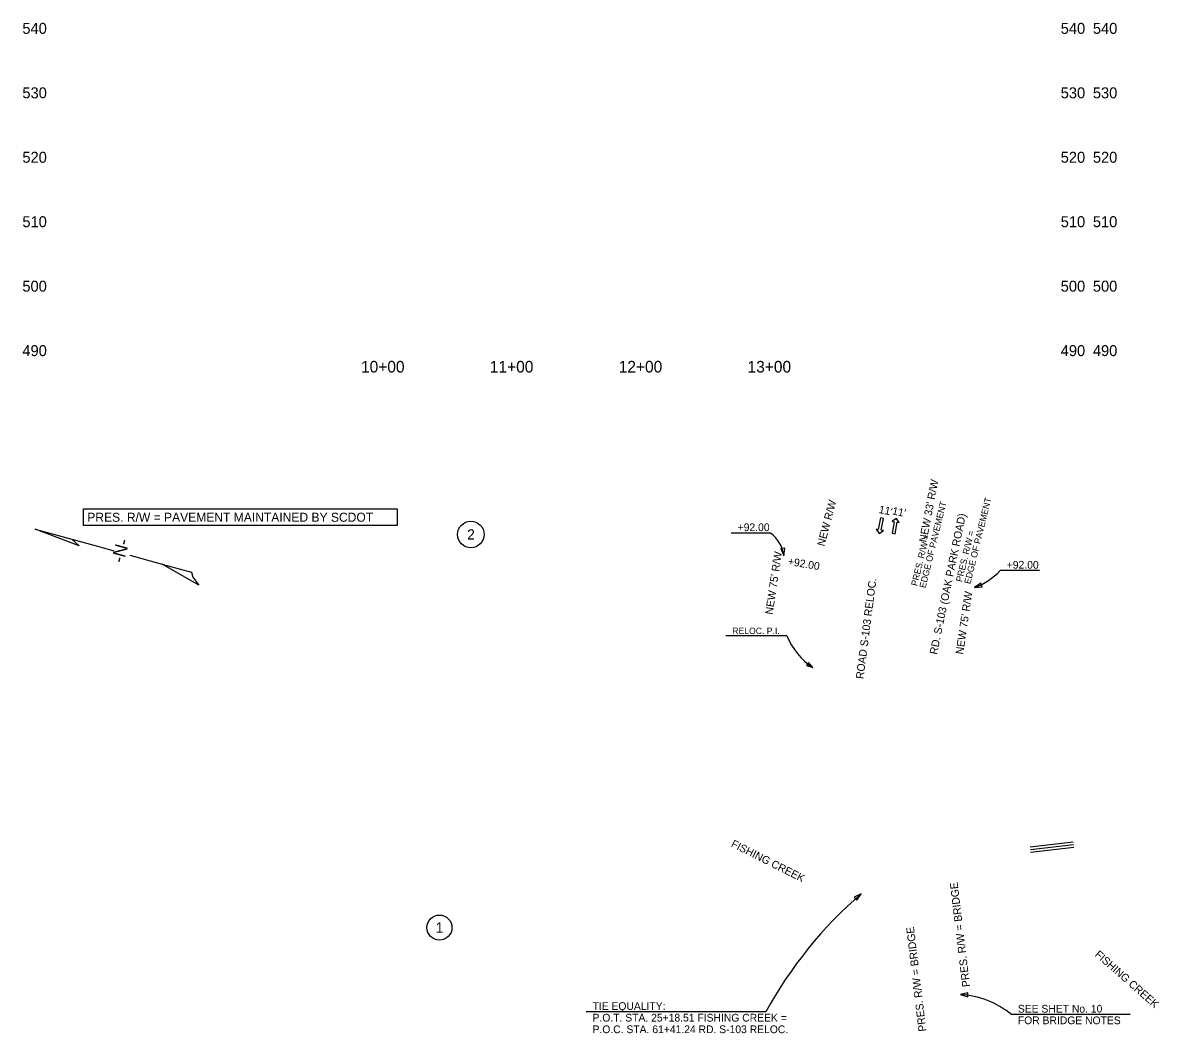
# Model space of a CAD drawing. Extents: x 1964377 to 1966966, y 1116414 to 1123213.
# Drawn here: x 1965294 to 1966176, y 1121651 to 1122435 of the extents above; entities that cross this region are included whole.
import ezdxf

# ---------------------------------------------------------------- set-up
doc = ezdxf.new("R2010")
doc.units = 0
for name, color, linetype in [('RD_DDB_Profile_Elev', 7, 'Continuous'), ('RD_DDB_StaTX', 7, 'Continuous'), ('RD_EX_Bridge', 7, 'Continuous'), ('RD_EX_DV_TX_Prop', 7, 'Continuous'), ('RD_EX_Misc', 7, 'Continuous'), ('RD_EX_RW_TX', 7, 'Continuous'), ('RD_HC_Data', 7, 'Continuous'), ('RD_HC_Data_Rel', 7, 'Continuous'), ('RD_PD_Final_LnLine', 7, 'Continuous'), ('RD_PD_Final_TX', 7, 'Continuous'), ('RD_PD_RW_TX', 7, 'Continuous'), ('RD_TX_RoadID', 7, 'Continuous')]:
    doc.layers.add(name, color=color, linetype=linetype)

msp = doc.modelspace()

# ---------------------------------------------------------------- linework, layer by layer
at = {"layer": 'RD_EX_Bridge'}
msp.add_line((1966153.67, 1121665.94), (1966061.4, 1121665.94), dxfattribs=at)
msp.add_lwpolyline([(1966027.63, 1121682.65), (1966021.76, 1121681.41), (1966027.46, 1121679.55)], close=True, dxfattribs=at)
msp.add_arc((1966018.08, 1121613.48), 68.03, 50.45527, 86.90064, dxfattribs=at)
at = {"layer": 'RD_EX_DV_TX_Prop'}
for centre, radius in [((1965641.86, 1122038.41), 10.35), ((1965617.52, 1121733.4), 9.72)]:
    msp.add_circle(centre, radius, dxfattribs=at)
at = {"layer": 'RD_EX_Misc'}
for p, q in [((1965337.87, 1122029.64), (1965303.66, 1122042.5)), ((1965303.66, 1122042.5), (1965332.24, 1122034.64)), ((1965332.24, 1122034.64), (1965352.05, 1122029.2)), ((1965332.24, 1122034.64), (1965337.87, 1122029.64)), ((1965352.05, 1122029.2), (1965364.69, 1122025.73)), ((1965377.3, 1122022.26), (1965402.27, 1122015.4)), ((1965402.27, 1122015.4), (1965406.05, 1122014.36)), ((1965430.69, 1121999.04), (1965402.27, 1122015.4)), ((1965406.05, 1122014.36), (1965425.19, 1122009.1))]:
    msp.add_line(p, q, dxfattribs=at)
msp.add_lwpolyline([(1965425.19, 1122009.1), (1965426.12, 1122005.17), (1965430.69, 1121999.04)], dxfattribs=at)
at = {"layer": 'RD_EX_RW_TX'}
msp.add_lwpolyline([(1965341.21, 1122058.26), (1965584.57, 1122058.26), (1965584.57, 1122045.26), (1965341.21, 1122045.26)], close=True, dxfattribs=at)
at = {"layer": 'RD_HC_Data'}
for p, q in [((1966075.84, 1121795.99), (1966109.27, 1121799.88)), ((1966076.07, 1121794.01), (1966109.5, 1121797.89)), ((1966076.3, 1121792.02), (1966109.74, 1121795.91)), ((1965870.75, 1121667.99), (1965731.31, 1121667.99))]:
    msp.add_line(p, q, dxfattribs=at)
msp.add_lwpolyline([(1965941.49, 1121754.74), (1965944.86, 1121759.71), (1965939.46, 1121757.09)], close=True, dxfattribs=at)
msp.add_arc((1966163.37, 1121507.36), 333.81, 130.8904, 151.23594, dxfattribs=at)
at = {"layer": 'RD_HC_Data_Rel'}
msp.add_line((1965887.22, 1121959.64), (1965839.77, 1121959.64), dxfattribs=at)
msp.add_lwpolyline([(1965902.46, 1121936.86), (1965907.2, 1121935.27), (1965903.89, 1121939.02)], close=True, dxfattribs=at)
msp.add_arc((1965936.85, 1121979.96), 53.63, 202.26306, 236.43447, dxfattribs=at)
at = {"layer": 'RD_PD_Final_LnLine'}
for points in [[(1965962.07, 1122050.75), (1965959.71, 1122051.18), (1965958.04, 1122042.17), (1965956.44, 1122042.46), (1965958.71, 1122039.17), (1965962, 1122041.43), (1965960.4, 1122041.73)], [(1965968.72, 1122039.29), (1965971.08, 1122038.85), (1965972.75, 1122047.87), (1965974.35, 1122047.57), (1965972.09, 1122050.87), (1965968.79, 1122048.6), (1965970.39, 1122048.3)]]:
    msp.add_lwpolyline(points, close=True, dxfattribs=at)
at = {"layer": 'RD_PD_RW_TX'}
for p, q in [((1965874.3, 1122039.48), (1965843.93, 1122039.48)), ((1966083.15, 1122010.36), (1966052.78, 1122010.36))]:
    msp.add_line(p, q, dxfattribs=at)
for points in [[(1965882.48, 1122027.44), (1965884.8, 1122021.9), (1965885.56, 1122027.85)], [(1966037.68, 1122000.69), (1966032.76, 1121997.25), (1966038.74, 1121997.77)]]:
    msp.add_lwpolyline(points, close=True, dxfattribs=at)
for centre, radius, start, end in [((1965859.03, 1122018.43), 26, 7.66789, 54.03618), ((1966014.99, 1122046.23), 52.1, 289.93818, 316.49462)]:
    msp.add_arc(centre, radius, start, end, dxfattribs=at)

# ---------------------------------------------------------------- texts
at = {"layer": 'RD_DDB_Profile_Elev'}
for s, p in [('540', (1965293.84, 1122426.8)), ('540', (1966099.66, 1122426.8)), ('540', (1966124.61, 1122426.8)), ('530', (1965293.84, 1122376.8)), ('530', (1966099.66, 1122376.8)), ('530', (1966124.61, 1122376.8)), ('520', (1965293.84, 1122326.8)), ('520', (1966099.66, 1122326.8)), ('520', (1966124.61, 1122326.8)), ('510', (1965293.84, 1122276.8)), ('510', (1966099.66, 1122276.8)), ('510', (1966124.61, 1122276.8)), ('500', (1965293.84, 1122226.8)), ('500', (1966099.66, 1122226.8)), ('500', (1966124.61, 1122226.8)), ('490', (1965293.84, 1122176.8)), ('490', (1966099.66, 1122176.8)), ('490', (1966124.61, 1122176.8))]:
    msp.add_text(s, height=8.5, dxfattribs=at).set_placement(p)
at = {"layer": 'RD_DDB_StaTX'}
for s, p in [('10+00', (1965556.62, 1122164.05)), ('11+00', (1965656.62, 1122164.05)), ('12+00', (1965756.62, 1122164.05)), ('13+00', (1965856.62, 1122164.05))]:
    msp.add_text(s, height=9, dxfattribs=at).set_placement(p)
at = {"layer": 'RD_EX_Bridge'}
for s, p in [('SEE SHET No. 10', (1966066.4, 1121667.44)), ('FOR BRIDGE NOTES', (1966066.4, 1121658.44))]:
    msp.add_text(s, height=6, dxfattribs=at).set_placement(p)
at = {"layer": 'RD_EX_DV_TX_Prop'}
for s, p in [('2', (1965639.03, 1122034.42)), ('1', (1965614.6, 1121729.41))]:
    msp.add_text(s, height=8, dxfattribs=at).set_placement(p)
at = {"layer": 'RD_EX_Misc'}
msp.add_text('-N-', height=10, rotation=74.63553, dxfattribs=at).set_placement((1965372.2, 1122015.59))
at = {"layer": 'RD_EX_RW_TX'}
for s, height, rotation, p in [('EDGE OF PAVEMENT', 5, 76.31414, (1966029.55, 1121999.61)), ('EDGE OF PAVEMENT', 5, 76.31414, (1965994.74, 1121996.49)), ('PRES. R/W = ', 5, 76.31414, (1966023.07, 1122001.18)), ('PRES. R/W = ', 5, 76.31414, (1965988.27, 1121998.07)), ('PRES. R/W = BRIDGE', 6, 96.83369, (1966029.3, 1121687.65)), ('PRES. R/W = BRIDGE', 6, 96.83369, (1965995.4, 1121653.11))]:
    msp.add_text(s, height=height, rotation=rotation, dxfattribs=at).set_placement(p)
msp.add_text('PRES. R/W = PAVEMENT MAINTAINED BY SCDOT', height=7, dxfattribs=at).set_placement((1965344.21, 1122048.26))
at = {"layer": 'RD_HC_Data'}
for s, p in [('TIE EQUALITY:', (1965736.31, 1121669.49)), ('P.O.T. STA. 25+18.51 FISHING CREEK =', (1965736.31, 1121660.49)), ('P.O.C. STA. 61+41.24 RD. S-103 RELOC.', (1965736.31, 1121651.49))]:
    msp.add_text(s, height=6, dxfattribs=at).set_placement(p)
at = {"layer": 'RD_HC_Data_Rel'}
msp.add_text('ROAD S-103 RELOC.', height=6, rotation=82.56231, dxfattribs=at).set_placement((1965946.52, 1121926))
msp.add_text('RELOC. P.I.', height=5, dxfattribs=at).set_placement((1965844.77, 1121961.14))
at = {"layer": 'RD_PD_Final_TX'}
for p in [(1965958.11, 1122055.16), (1965968.52, 1122054.07)]:
    msp.add_text("11'", height=6, rotation=348.23568, dxfattribs=at).set_placement(p)
at = {"layer": 'RD_PD_RW_TX'}
for s, rotation, p in [("NEW 33' R/W", 79.11367, (1965995.5, 1122032.02)), ('NEW R/W', 75.19763, (1965916.24, 1122028.84)), ("NEW 75' R/W", 81.5547, (1965876.1, 1121975.97)), ('+92.00', 350.54277, (1965887.61, 1122014.77)), ("NEW 75' R/W", 81.5547, (1966023.93, 1121945.07))]:
    msp.add_text(s, height=6, rotation=rotation, dxfattribs=at).set_placement(p)
for p in [(1965848.93, 1122040.98), (1966057.78, 1122011.86)]:
    msp.add_text('+92.00', height=6, dxfattribs=at).set_placement(p)
at = {"layer": 'RD_TX_RoadID'}
for s, rotation, p in [('RD. S-103 (OAK PARK ROAD)', 78.3408, (1966003.66, 1121944.89)), ('FISHING CREEK', 333.24595, (1965843.27, 1121796.51)), ('FISHING CREEK', 318.62321, (1966125.64, 1121711.77))]:
    msp.add_text(s, height=6, rotation=rotation, dxfattribs=at).set_placement(p)

doc.saveas('drawing.dxf')
